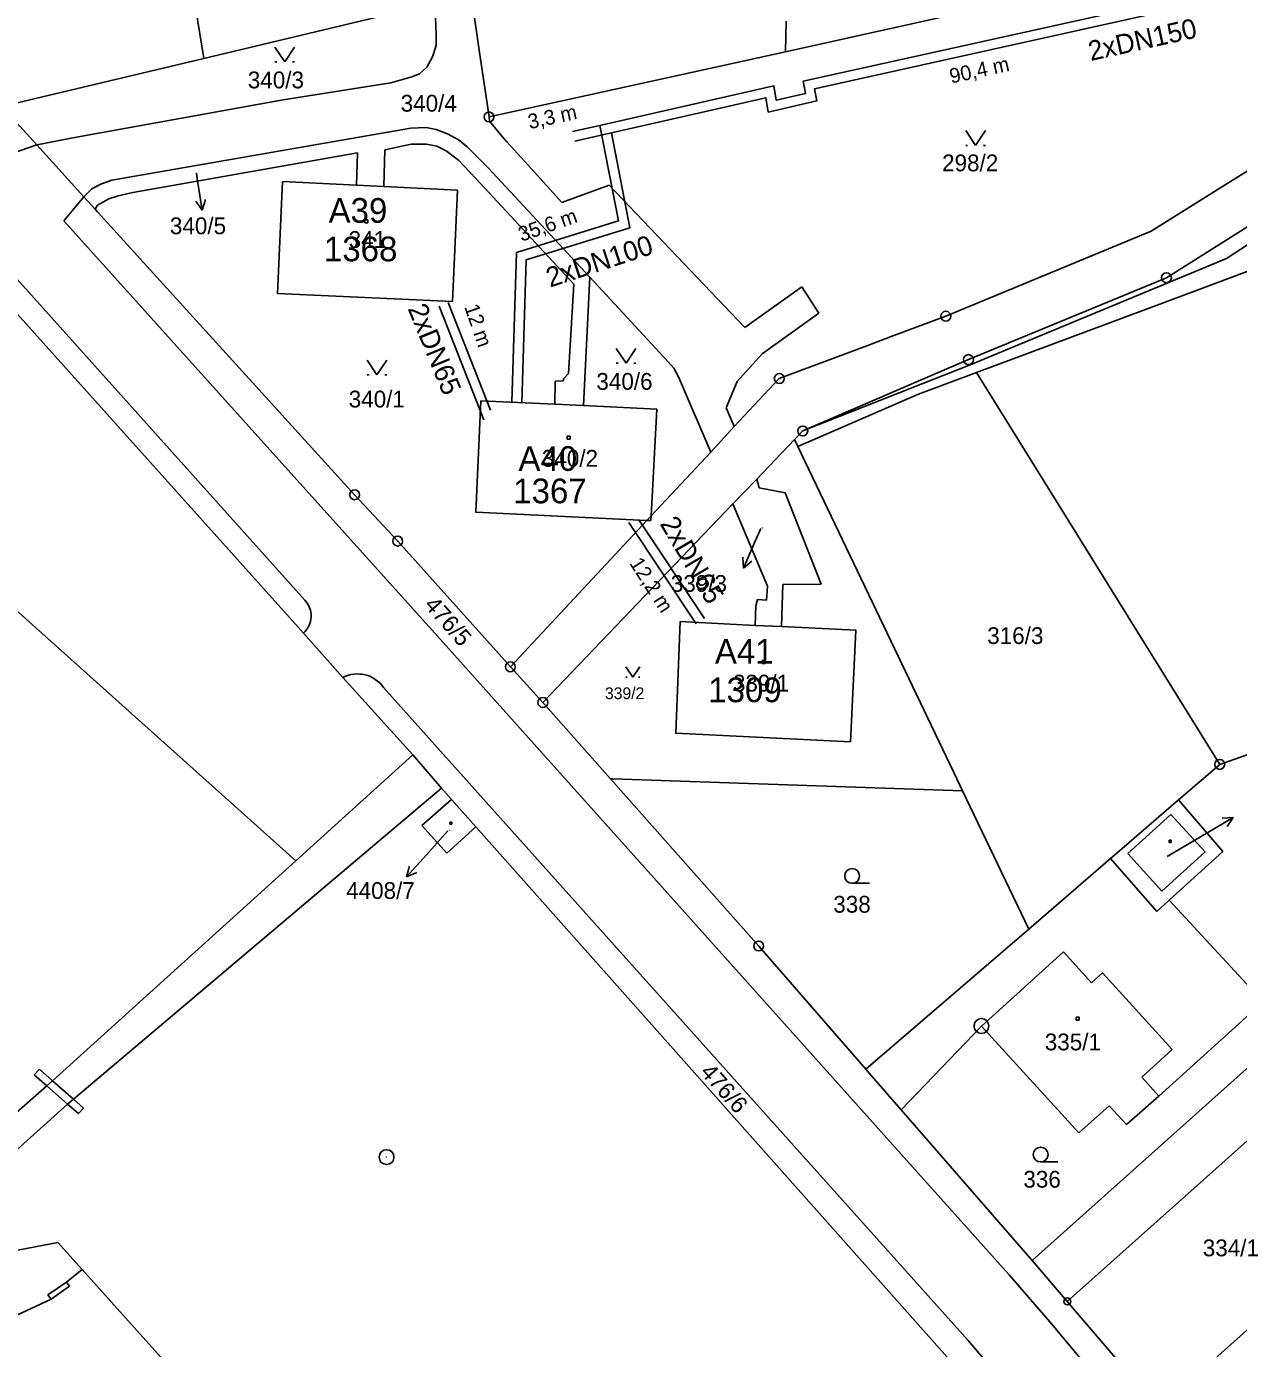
# Model space of a CAD drawing. Extents: x -468021 to -466942, y -1130484 to -1128584.
# Drawn here: x -467636.6 to -467513.8, y -1129521.7 to -1129387.9 of the extents above; entities that cross this region are included whole.
import ezdxf

# ---------------------------------------------------------------- set-up
doc = ezdxf.new("R2010")
doc.units = 0
for name, color, linetype in [('21-Označení-odběrného-místa', 7, 'Continuous'), ('22-Odběrná místa-šrafy', 7, 'Continuous'), ('25-Popisná-čísla', 7, 'Continuous'), ('27-delky-vedeni', 7, 'Continuous'), ('DKM', 7, 'Continuous'), ('UT_SKUTEČNOST_staré', 7, 'Continuous')]:
    doc.layers.add(name, color=color, linetype=linetype)

msp = doc.modelspace()

# ---------------------------------------------------------------- linework, layer by layer
at = {"layer": '22-Odběrná místa-šrafy'}
for points in [[(-467611.16, -1129414.91), (-467593.42, -1129415.73), (-467592.91, -1129404.46), (-467600.4, -1129404.09), (-467603.16, -1129403.96), (-467610.64, -1129403.59), (-467611.16, -1129414.91)], [(-467583.06, -1129426.14), (-467590.55, -1129425.79), (-467591.08, -1129437.05), (-467573.74, -1129437.89), (-467573.3, -1129437.43), (-467572.74, -1129426.62), (-467580.18, -1129426.27), (-467583.06, -1129426.14)], [(-467560.11, -1129448.65), (-467562.77, -1129448.52), (-467570.37, -1129448.14), (-467570.83, -1129459.45), (-467553.13, -1129460.3), (-467552.57, -1129449.02), (-467560.11, -1129448.65)]]:
    msp.add_lwpolyline(points, dxfattribs=at)
at = {"layer": 'DKM'}
for p, q in [((-467711.58, -1129330.9), (-467608.39, -1129445.98)), ((-467711.94, -1129334.02), (-467609.05, -1129448.72)), ((-467609.29, -1129472.35), (-467740.28, -1129355.1)), ((-467618.63, -1129391.12), (-467623.72, -1129359)), ((-467595.08, -1129388.65), (-467595.22, -1129385.28)), ((-467591.43, -1129385.36), (-467590.68, -1129390.51)), ((-467618.63, -1129391.12), (-467596.01, -1129385.73)), ((-467540.22, -1129386.14), (-467559.72, -1129390.44)), ((-467559.72, -1129390.44), (-467559.64, -1129387.34)), ((-467595.08, -1129389.8), (-467595.08, -1129388.65)), ((-467611.42, -1129389.97), (-467610.42, -1129391.47)), ((-467610.42, -1129391.47), (-467609.42, -1129389.97)), ((-467595.46, -1129390.95), (-467595.08, -1129389.8)), ((-467590.68, -1129390.51), (-467589.73, -1129397.04)), ((-467559.72, -1129390.44), (-467579.85, -1129394.87)), ((-467639.07, -1129395.99), (-467618.63, -1129391.12)), ((-467611.42, -1129391.47), (-467611.22, -1129391.47)), ((-467609.62, -1129391.47), (-467609.42, -1129391.47)), ((-467596.76, -1129392.69), (-467596.04, -1129392.02)), ((-467596.04, -1129392.02), (-467595.46, -1129390.95)), ((-467599.69, -1129393.59), (-467597.55, -1129392.99)), ((-467597.55, -1129392.99), (-467596.76, -1129392.69)), ((-467610.57, -1129395.31), (-467599.69, -1129393.59)), ((-467639.07, -1129395.99), (-467635.54, -1129399.87)), ((-467631.51, -1129399.1), (-467610.57, -1129395.31)), ((-467579.85, -1129394.87), (-467589.73, -1129397.04)), ((-467589.73, -1129397.04), (-467589.69, -1129397.48)), ((-467627.93, -1129403.46), (-467597.66, -1129398.18)), ((-467597.66, -1129398.18), (-467596.09, -1129398.12)), ((-467596.09, -1129398.12), (-467595.09, -1129398.31)), ((-467595.09, -1129398.31), (-467593.86, -1129398.8)), ((-467589.69, -1129397.48), (-467588.4, -1129399.01)), ((-467541.46, -1129398.43), (-467540.46, -1129399.93)), ((-467540.46, -1129399.93), (-467539.46, -1129398.43)), ((-467635.54, -1129399.87), (-467638.74, -1129400.97)), ((-467635.54, -1129399.87), (-467631.51, -1129399.1)), ((-467635.54, -1129399.87), (-467630.77, -1129405.12)), ((-467597.63, -1129399.81), (-467600.28, -1129400.38)), ((-467596.05, -1129399.8), (-467597.63, -1129399.81)), ((-467595.01, -1129399.99), (-467596.05, -1129399.8)), ((-467594.06, -1129400.48), (-467595.01, -1129399.99)), ((-467593.86, -1129398.8), (-467592.77, -1129399.4)), ((-467592.77, -1129399.4), (-467591.93, -1129400.06)), ((-467591.93, -1129400.06), (-467589.83, -1129402.21)), ((-467588.4, -1129399.01), (-467588.16, -1129399.29)), ((-467587.92, -1129399.55), (-467588.16, -1129399.29)), ((-467585.78, -1129401.92), (-467587.92, -1129399.55)), ((-467541.46, -1129399.93), (-467541.26, -1129399.93)), ((-467539.66, -1129399.93), (-467539.46, -1129399.93)), ((-467521.13, -1129413.33), (-467498.17, -1129398.86)), ((-467603.06, -1129400.69), (-467625.79, -1129404.68)), ((-467603.16, -1129403.96), (-467603.06, -1129400.69)), ((-467600.28, -1129400.38), (-467600.4, -1129404.09)), ((-467592.84, -1129401.41), (-467594.06, -1129400.48)), ((-467591.67, -1129402.64), (-467592.84, -1129401.41)), ((-467515.19, -1129403.92), (-467510.66, -1129401.09)), ((-467497.93, -1129400.13), (-467515.04, -1129411.38)), ((-467619.37, -1129402.74), (-467619.25, -1129403.51)), ((-467591.67, -1129402.64), (-467591.04, -1129403.3)), ((-467579.52, -1129413.26), (-467589.83, -1129402.21)), ((-467582.36, -1129405.71), (-467585.78, -1129401.92)), ((-467629.96, -1129404.33), (-467628.99, -1129403.82)), ((-467628.99, -1129403.82), (-467627.93, -1129403.46)), ((-467619.25, -1129403.51), (-467618.79, -1129406.47)), ((-467611.16, -1129414.91), (-467610.64, -1129403.59)), ((-467610.64, -1129403.59), (-467603.16, -1129403.96)), ((-467603.16, -1129403.96), (-467600.4, -1129404.09)), ((-467600.4, -1129404.09), (-467592.91, -1129404.46)), ((-467591.04, -1129403.3), (-467581.16, -1129413.98)), ((-467582.36, -1129405.71), (-467577.57, -1129403.95)), ((-467577.57, -1129403.95), (-467563.81, -1129418.36)), ((-467522.69, -1129408.6), (-467515.19, -1129403.92)), ((-467632.8, -1129407.57), (-467630.77, -1129405.12)), ((-467630.77, -1129405.12), (-467629.96, -1129404.33)), ((-467630.77, -1129405.12), (-467629.61, -1129406.4)), ((-467628.24, -1129405.35), (-467629.37, -1129405.98)), ((-467627.3, -1129405.04), (-467628.24, -1129405.35)), ((-467625.79, -1129404.68), (-467627.3, -1129405.04)), ((-467618.79, -1129406.47), (-467618.45, -1129405.41)), ((-467592.91, -1129404.46), (-467593.42, -1129415.73)), ((-467493.48, -1129405.38), (-467521.54, -1129415.91)), ((-467629.37, -1129405.98), (-467629.61, -1129406.4)), ((-467629.61, -1129406.4), (-467629.37, -1129406.67)), ((-467629.37, -1129406.67), (-467603.35, -1129435.3)), ((-467618.79, -1129406.47), (-467619.44, -1129405.56)), ((-467594.94, -1129449.61), (-467632.8, -1129407.57)), ((-467602.31, -1129407.47), (-467602.01, -1129407.47)), ((-467602.31, -1129407.77), (-467602.31, -1129407.47)), ((-467602.01, -1129407.77), (-467602.31, -1129407.77)), ((-467602.01, -1129407.47), (-467602.01, -1129407.77)), ((-467543.47, -1129417.22), (-467522.69, -1129408.6)), ((-467541.02, -1129422.13), (-467515.04, -1129411.38)), ((-467580.18, -1129426.27), (-467579.52, -1129413.26)), ((-467579.52, -1129413.26), (-467571.59, -1129421.85)), ((-467541.18, -1129421.61), (-467521.13, -1129413.33)), ((-467581.16, -1129413.98), (-467581.69, -1129423.02)), ((-467558.06, -1129414.23), (-467563.81, -1129418.36)), ((-467556.34, -1129416.92), (-467558.06, -1129414.23)), ((-467593.42, -1129415.73), (-467611.16, -1129414.91)), ((-467540.35, -1129422.93), (-467521.54, -1129415.91)), ((-467562.07, -1129421.04), (-467556.34, -1129416.92)), ((-467549.01, -1129419.29), (-467543.47, -1129417.22)), ((-467560.34, -1129423.53), (-467551.19, -1129420.11)), ((-467551.19, -1129420.11), (-467549.01, -1129419.29)), ((-467576.86, -1129420.48), (-467575.86, -1129421.98)), ((-467575.86, -1129421.98), (-467574.86, -1129420.48)), ((-467564.59, -1129423.83), (-467562.07, -1129421.04)), ((-467602.08, -1129421.67), (-467601.08, -1129423.17)), ((-467601.08, -1129423.17), (-467600.08, -1129421.67)), ((-467576.86, -1129421.98), (-467576.66, -1129421.98)), ((-467575.06, -1129421.98), (-467574.86, -1129421.98)), ((-467571.59, -1129421.85), (-467571.03, -1129422.47)), ((-467571.03, -1129422.47), (-467570.56, -1129423.35)), ((-467557.96, -1129428.84), (-467541.18, -1129421.61)), ((-467541.02, -1129422.13), (-467557.96, -1129428.84)), ((-467602.08, -1129423.17), (-467601.88, -1129423.17)), ((-467600.28, -1129423.17), (-467600.08, -1129423.17)), ((-467583.03, -1129423.79), (-467583.06, -1129426.14)), ((-467582.24, -1129423.77), (-467583.03, -1129423.79)), ((-467582.17, -1129423.54), (-467582.24, -1129423.77)), ((-467581.69, -1129423.02), (-467582.17, -1129423.54)), ((-467570.56, -1129423.35), (-467567.28, -1129430.97)), ((-467565.7, -1129426.49), (-467564.59, -1129423.83)), ((-467560.34, -1129423.53), (-467564.89, -1129428.4)), ((-467546.24, -1129425.13), (-467540.35, -1129422.93)), ((-467540.35, -1129422.93), (-467515.73, -1129462.6)), ((-467546.24, -1129425.13), (-467558.47, -1129430.41)), ((-467590.55, -1129425.79), (-467591.08, -1129437.05)), ((-467583.06, -1129426.14), (-467590.55, -1129425.79)), ((-467580.18, -1129426.27), (-467583.06, -1129426.14)), ((-467572.74, -1129426.62), (-467580.18, -1129426.27)), ((-467573.3, -1129437.43), (-467572.74, -1129426.62)), ((-467564.89, -1129428.4), (-467565.7, -1129426.49)), ((-467581.83, -1129429.37), (-467581.53, -1129429.37)), ((-467581.83, -1129429.67), (-467581.83, -1129429.37)), ((-467581.53, -1129429.37), (-467581.53, -1129429.67)), ((-467564.89, -1129428.4), (-467567.28, -1129430.97)), ((-467558.8, -1129429.72), (-467557.96, -1129428.84)), ((-467581.53, -1129429.67), (-467581.83, -1129429.67)), ((-467562.62, -1129433.71), (-467558.8, -1129429.72)), ((-467558.47, -1129430.41), (-467558.8, -1129429.72)), ((-467542.66, -1129463.43), (-467558.47, -1129430.41)), ((-467567.28, -1129430.97), (-467573.3, -1129437.43)), ((-467565.03, -1129436.23), (-467562.62, -1129433.71)), ((-467562.39, -1129434.59), (-467562.62, -1129433.71)), ((-467559.73, -1129435.11), (-467562.39, -1129434.59)), ((-467598.98, -1129439.99), (-467603.35, -1129435.3)), ((-467584.28, -1129456.33), (-467565.03, -1129436.23)), ((-467565.03, -1129436.23), (-467561.54, -1129444.54)), ((-467556.08, -1129444.34), (-467559.73, -1129435.11)), ((-467591.08, -1129437.05), (-467573.74, -1129437.89)), ((-467573.3, -1129437.43), (-467573.74, -1129437.89)), ((-467573.33, -1129437.91), (-467573.3, -1129437.43)), ((-467573.74, -1129437.89), (-467587.57, -1129452.72)), ((-467573.74, -1129437.89), (-467573.33, -1129437.91)), ((-467562.21, -1129438.7), (-467562.77, -1129439.99)), ((-467587.57, -1129452.72), (-467598.98, -1129439.99)), ((-467562.77, -1129439.99), (-467563.96, -1129442.74)), ((-467563.96, -1129442.74), (-467564.02, -1129441.62)), ((-467563.96, -1129442.74), (-467563.11, -1129442.02)), ((-467561.54, -1129444.54), (-467561.62, -1129445.96)), ((-467560.11, -1129448.65), (-467559.97, -1129444.4)), ((-467559.97, -1129444.4), (-467556.08, -1129444.34)), ((-467562.7, -1129446.55), (-467562.77, -1129448.52)), ((-467562.56, -1129445.89), (-467562.7, -1129446.55)), ((-467561.62, -1129445.96), (-467562.56, -1129445.89)), ((-467570.37, -1129448.14), (-467570.83, -1129459.45)), ((-467562.77, -1129448.52), (-467570.37, -1129448.14)), ((-467609.05, -1129448.72), (-467608.53, -1129449.3)), ((-467608.53, -1129449.3), (-467604.53, -1129453.8)), ((-467537.05, -1129514.29), (-467594.94, -1129449.61)), ((-467560.11, -1129448.65), (-467562.77, -1129448.52)), ((-467552.57, -1129449.02), (-467560.11, -1129448.65)), ((-467553.13, -1129460.3), (-467552.57, -1129449.02)), ((-467562.08, -1129452.07), (-467561.78, -1129452.07)), ((-467562.08, -1129452.37), (-467562.08, -1129452.07)), ((-467561.78, -1129452.07), (-467561.78, -1129452.37)), ((-467584.28, -1129456.33), (-467587.57, -1129452.72)), ((-467575.87, -1129452.72), (-467575.17, -1129453.77)), ((-467575.17, -1129453.77), (-467574.47, -1129452.72)), ((-467561.78, -1129452.37), (-467562.08, -1129452.37)), ((-467597.44, -1129461.64), (-467604.53, -1129453.8)), ((-467575.87, -1129453.77), (-467575.73, -1129453.77)), ((-467574.61, -1129453.77), (-467574.47, -1129453.77)), ((-467515.73, -1129462.6), (-467492.47, -1129454.28)), ((-467577.43, -1129464.05), (-467584.28, -1129456.33)), ((-467570.83, -1129459.45), (-467553.13, -1129460.3)), ((-467597.44, -1129461.64), (-467609.29, -1129472.35)), ((-467594.56, -1129465.01), (-467597.44, -1129461.64)), ((-467515.73, -1129462.6), (-467519.91, -1129466.2)), ((-467577.24, -1129464.06), (-467577.43, -1129464.05)), ((-467562.42, -1129480.99), (-467577.43, -1129464.05)), ((-467541.77, -1129465.29), (-467577.24, -1129464.06)), ((-467541.77, -1129465.29), (-467542.66, -1129463.43)), ((-467594.56, -1129465.01), (-467631.81, -1129496.49)), ((-467593.53, -1129466.16), (-467594.56, -1129465.01)), ((-467535.08, -1129479.27), (-467541.77, -1129465.29)), ((-467593.53, -1129466.16), (-467596.54, -1129468.79)), ((-467591.07, -1129468.93), (-467593.53, -1129466.16)), ((-467519.91, -1129466.2), (-467525.65, -1129471.15)), ((-467515.42, -1129471.42), (-467519.91, -1129466.2)), ((-467520.68, -1129467.66), (-467525.05, -1129471.62)), ((-467517.21, -1129471.44), (-467520.68, -1129467.66)), ((-467516.95, -1129469.49), (-467514.37, -1129467.96)), ((-467514.37, -1129467.96), (-467515.48, -1129468.04)), ((-467514.37, -1129467.96), (-467514.97, -1129468.9)), ((-467596.54, -1129468.79), (-467594.02, -1129471.59)), ((-467593.9, -1129469.33), (-467596.08, -1129471.74)), ((-467594.02, -1129471.59), (-467591.07, -1129468.93)), ((-467593.71, -1129468.44), (-467593.5, -1129468.44)), ((-467593.71, -1129468.65), (-467593.71, -1129468.44)), ((-467593.5, -1129468.65), (-467593.71, -1129468.65)), ((-467593.5, -1129468.44), (-467593.5, -1129468.65)), ((-467529.62, -1129538.01), (-467591.07, -1129468.93)), ((-467521.04, -1129471.91), (-467516.95, -1129469.49)), ((-467520.85, -1129470.28), (-467520.64, -1129470.28)), ((-467520.85, -1129470.49), (-467520.85, -1129470.28)), ((-467520.64, -1129470.49), (-467520.85, -1129470.49)), ((-467520.64, -1129470.28), (-467520.64, -1129470.49)), ((-467609.29, -1129472.35), (-467633.93, -1129494.62)), ((-467596.08, -1129471.74), (-467598.09, -1129473.97)), ((-467526.78, -1129472.12), (-467535.08, -1129479.27)), ((-467525.65, -1129471.15), (-467526.78, -1129472.12)), ((-467526.78, -1129472.12), (-467522.11, -1129477.49)), ((-467525.05, -1129471.62), (-467521.59, -1129475.42)), ((-467521.59, -1129475.42), (-467517.21, -1129471.44)), ((-467520.85, -1129476.35), (-467515.42, -1129471.42)), ((-467598.09, -1129473.97), (-467597.79, -1129472.89)), ((-467598.09, -1129473.97), (-467597.05, -1129473.56)), ((-467552.96, -1129474.64), (-467551.21, -1129474.64)), ((-467522.11, -1129477.49), (-467520.85, -1129476.35)), ((-467520.85, -1129476.35), (-467511.34, -1129486.64)), ((-467535.08, -1129479.27), (-467551.57, -1129493.47)), ((-467551.57, -1129493.47), (-467562.42, -1129480.99)), ((-467531.55, -1129481.59), (-467539.86, -1129489.09)), ((-467528.72, -1129484.72), (-467531.55, -1129481.59)), ((-467528.72, -1129484.72), (-467527.6, -1129483.71)), ((-467520.54, -1129491.46), (-467527.6, -1129483.71)), ((-467511.34, -1129486.64), (-467521.91, -1129496.18)), ((-467530.28, -1129488.2), (-467529.98, -1129488.2)), ((-467530.28, -1129488.5), (-467530.28, -1129488.2)), ((-467529.98, -1129488.2), (-467529.98, -1129488.5)), ((-467539.86, -1129489.09), (-467548, -1129497.57)), ((-467539.86, -1129489.09), (-467530, -1129499.91)), ((-467508.67, -1129489.53), (-467534.72, -1129512.83)), ((-467529.98, -1129488.5), (-467530.28, -1129488.5)), ((-467520.54, -1129491.46), (-467523.62, -1129494.27)), ((-467635.79, -1129494.03), (-467635.27, -1129493.44)), ((-467633.93, -1129494.62), (-467635.27, -1129493.44)), ((-467551.24, -1129493.85), (-467551.57, -1129493.47)), ((-467635.79, -1129494.03), (-467634.51, -1129495.15)), ((-467633.93, -1129494.62), (-467634.51, -1129495.15)), ((-467631.81, -1129496.49), (-467633.93, -1129494.62)), ((-467548, -1129497.57), (-467551.24, -1129493.85)), ((-467523.62, -1129494.27), (-467521.91, -1129496.18)), ((-467634.51, -1129495.15), (-467649.97, -1129508.67)), ((-467634.51, -1129495.15), (-467632.41, -1129497)), ((-467525.16, -1129499.07), (-467521.91, -1129496.18)), ((-467632.41, -1129497), (-467648.55, -1129511.48)), ((-467631.81, -1129496.49), (-467632.41, -1129497)), ((-467632.41, -1129497), (-467631.32, -1129497.96)), ((-467630.79, -1129497.39), (-467631.81, -1129496.49)), ((-467631.32, -1129497.96), (-467630.79, -1129497.39)), ((-467534.72, -1129512.83), (-467548, -1129497.57)), ((-467530, -1129499.91), (-467526.92, -1129497.17)), ((-467526.92, -1129497.17), (-467525.16, -1129499.07)), ((-467510.13, -1129498.18), (-467531.17, -1129516.97)), ((-467533.87, -1129502.85), (-467532.12, -1129502.85)), ((-467521.88, -1129527.82), (-467497.41, -1129505.93)), ((-467642.29, -1129512.68), (-467633.4, -1129511.01)), ((-467633.4, -1129511.01), (-467630.94, -1129513.74)), ((-467630.94, -1129513.74), (-467632.53, -1129515.03)), ((-467630.94, -1129513.74), (-467621.51, -1129524.22)), ((-467531.17, -1129516.97), (-467534.72, -1129512.83)), ((-467632.53, -1129515.03), (-467634.41, -1129516.3)), ((-467632.22, -1129515.42), (-467632.53, -1129515.03)), ((-467537.05, -1129514.29), (-467532.94, -1129519.04)), ((-467634.41, -1129516.3), (-467634.06, -1129516.75)), ((-467634.06, -1129516.75), (-467632.22, -1129515.42)), ((-467634.06, -1129516.75), (-467660.11, -1129528.84)), ((-467521.88, -1129527.82), (-467531.17, -1129516.97)), ((-467532.94, -1129519.04), (-467521.7, -1129532.44))]:
    msp.add_line(p, q, dxfattribs=at)
msp.add_lwpolyline([(-467521.55, -1129544.82), (-467527.93, -1129536.59), (-467541.21, -1129520.91), (-467600.42, -1129454.8)], dxfattribs=at)
for centre, radius in [((-467589.73, -1129397.04), 0.5), ((-467589.73, -1129397.04), 0.01), ((-467521.13, -1129413.33), 0.5), ((-467521.13, -1129413.33), 0.01), ((-467543.47, -1129417.22), 0.5), ((-467543.47, -1129417.22), 0.01), ((-467541.18, -1129421.61), 0.5), ((-467541.18, -1129421.61), 0.01), ((-467560.34, -1129423.53), 0.5), ((-467560.34, -1129423.53), 0.01), ((-467557.96, -1129428.84), 0.5), ((-467557.96, -1129428.84), 0.01), ((-467603.35, -1129435.3), 0.5), ((-467603.35, -1129435.3), 0.01), ((-467598.98, -1129439.99), 0.5), ((-467598.98, -1129439.99), 0.01), ((-467587.57, -1129452.72), 0.5), ((-467587.57, -1129452.72), 0.01), ((-467584.28, -1129456.33), 0.5), ((-467584.28, -1129456.33), 0.01), ((-467515.73, -1129462.6), 0.5), ((-467515.73, -1129462.6), 0.01), ((-467552.96, -1129473.89), 0.75), ((-467562.42, -1129480.99), 0.5), ((-467562.42, -1129480.99), 0.01), ((-467539.86, -1129489.09), 0.75), ((-467539.86, -1129489.09), 0.01), ((-467600.11, -1129502.36), 0.75), ((-467533.87, -1129502.1), 0.75), ((-467600.11, -1129502.36), 0.01), ((-467531.17, -1129516.97), 0.35), ((-467531.17, -1129516.97), 0.007)]:
    msp.add_circle(centre, radius, dxfattribs=at)
for centre, radius, start, end in [((-467610.05, -1129447.57), 2.3, 311.3568, 43.8139), ((-467603.05, -1129456.67), 3.23, 35.4316, 117.2187)]:
    msp.add_arc(centre, radius, start, end, dxfattribs=at)
at = {"layer": 'UT_SKUTEČNOST_staré'}
for points in [[(-467492.81, -1129379), (-467557.92, -1129393.43), (-467557.68, -1129394.67), (-467560.64, -1129395.35), (-467560.88, -1129393.91), (-467578.5, -1129397.9)], [(-467491.74, -1129379.76), (-467556.76, -1129394.19), (-467556.52, -1129395.43), (-467561.45, -1129396.56), (-467561.69, -1129395.11), (-467577.33, -1129398.65)], [(-467578.5, -1129397.9), (-467576.62, -1129407.58), (-467586.96, -1129410.77), (-467587.42, -1129425.94)], [(-467577.33, -1129398.65), (-467575.47, -1129408.27), (-467585.98, -1129411.52), (-467586.42, -1129425.98)], [(-467581.27, -1129398.51), (-467578.5, -1129397.9)], [(-467577.33, -1129398.65), (-467581.05, -1129399.49)], [(-467593.86, -1129415.84), (-467589.57, -1129426.73)], [(-467594.79, -1129416.2), (-467590.26, -1129427.71)], [(-467575.57, -1129438.11), (-467568.74, -1129448.38)], [(-467574.55, -1129437.83), (-467567.91, -1129447.82)]]:
    msp.add_lwpolyline(points, dxfattribs=at)

# ---------------------------------------------------------------- texts
at = {"layer": '21-Označení-odběrného-místa'}
for s, p in [('A39', (-467605.98, -1129407.76)), ('A40', (-467586.75, -1129432.88)), ('A41', (-467566.86, -1129452.4))]:
    msp.add_text(s, height=2.5, dxfattribs=at).set_placement(p)
at = {"layer": '25-Popisná-čísla'}
for s, p in [('1368', (-467606.45, -1129411.66)), ('1367', (-467587.28, -1129436.16)), ('1309', (-467567.53, -1129456.3))]:
    msp.add_text(s, height=2.5, dxfattribs=at).set_placement(p)
at = {"layer": '27-delky-vedeni'}
for s, rotation, p in [('90,4 m', 12.3172, (-467542.92, -1129393.67)), ('3,3 m', 12.3172, (-467585.62, -1129398.29)), ('35,6 m', 19.1556, (-467586.45, -1129409.69)), ('12 m', 289.1556, (-467592.25, -1129416.28)), ('12,2 m', 302.638, (-467575.56, -1129442.23))]:
    msp.add_text(s, height=1.5, rotation=rotation, dxfattribs=at).set_placement(p)
at = {"layer": 'DKM'}
for s, height, p in [('340/3', 1.7, (-467614.16, -1129394.15)), ('340/4', 1.7, (-467598.68, -1129396.51)), ('298/2', 1.7, (-467543.85, -1129402.55)), ('340/5', 0.1, (-467619.58, -1129402.74)), ('340/5', 1.7, (-467622.05, -1129408.92)), ('341', 1.7, (-467603.95, -1129410.31)), ('340/6', 1.7, (-467578.86, -1129424.67)), ('340/1', 1.7, (-467603.94, -1129426.46)), ('340/2', 1.7, (-467584.38, -1129432.46)), ('339/3', 0.1, (-467562.21, -1129438.7)), ('339/3', 1.7, (-467571.32, -1129445.13)), ('316/3', 1.7, (-467539.28, -1129450.41)), ('339/1', 1.7, (-467565.03, -1129455.22)), ('339/2', 1.19, (-467577.99, -1129455.99)), ('4408/7', 0.1, (-467593.9, -1129469.33)), ('335/2', 0.1, (-467521.04, -1129471.91)), ('4408/7', 1.7, (-467604.2, -1129476.22)), ('338', 1.7, (-467554.87, -1129477.61)), ('335/1', 1.7, (-467533.45, -1129491.55)), ('336', 1.7, (-467535.62, -1129505.45)), ('334/1', 1.7, (-467517.45, -1129512.4))]:
    msp.add_text(s, height=height, dxfattribs=at).set_placement(p)
for s, rotation, p in [('476/5', 311.3312, (-467596.38, -1129446.52)), ('476/6', 311.5352, (-467568.43, -1129493.82))]:
    msp.add_text(s, height=1.7, rotation=rotation, dxfattribs=at).set_placement(p)
at = {"layer": 'UT_SKUTEČNOST_staré'}
for s, rotation, p in [('2xDN150', 12.4706, (-467528.8, -1129391.39)), ('2xDN100', 18.1308, (-467583.55, -1129414.33)), ('2xDN65', 292.3294, (-467597.99, -1129416.45)), ('2xDN65', 300.6281, (-467572.48, -1129438.23))]:
    msp.add_text(s, height=2, rotation=rotation, dxfattribs=at).set_placement(p)

doc.saveas('drawing.dxf')
